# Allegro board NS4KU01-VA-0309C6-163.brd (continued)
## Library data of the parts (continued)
AB1 AB2 AB5 AB6 AB9 AB10 B2 B4 B8-B11 B19 B22 R15-R17 R20 R25 R26 R43 R46 R51 R55 R102 R106 R125 R145 R165 R182 R198 R230 R235 R245 R264 R329 R418 R477 R480 R514 R532 R549 R562 R563 R638 R670-R672 R3406 R3416 R3425 R3432 R3437 R3443 R3447 R3448 RT1 RT2 RT6 RT7 = M-R0603
AB4 AB7 AB8 AB11-AB17 AR3-AR15 B1 B5 B16-B18 ER1 ER2 R1-R14 R18 R19 R21-R24 R27-R38 R41 R42 R50 R52-R54 R56-R77 R79-R83 R85-R101 R103-R105 R107-R124 R126-R136 R138-R144 R147-R155 R157-R161 R163 R164 R167 R168 R170 R171 R173 R174 R176 R177 R179 R180 R184 R185 R187-R197 R199-R202 R204 R205 R207 R210-R229 R231-R234 R236-R244 R246-R258 R260-R263 R265-R328 R330-R392 R395-R414 R416 R420-R432 R434-R443 R448-R457 R460-R467 R469 R472-R476 R478 R479 R481-R513 R515-R531 R533 R534 R537 R539-R542 R545-R548 R550-R554 R557-R559 R561 R564-R568 R576-R579 R581-R604 R621 R622 R625 R637 R639 R643 R645-R648 R650 R651 R653 R658 R660 R668 R669 R687-R691 R695-R701 R710 R738-R743 R745 R784 R837-R844 R3058 R3085 R3087 R3095 R3152-R3154 R3160 R3161 R3163 R3164 R3197 R3198 R3201 R3214 R3232 R3239 R3243 R3247-R3253 R3255 R3258 R3278-R3281 R3294 R3310 R3321-R3323 R3370 R3386 R3401-R3403 R3405 R3407-R3410 R3413-R3415 R3417 R3421 R3422 R3426 R3428-R3431 R3433 R3434 R3436 R3439 R3440 R3442 R3444-R3446 R3449-R3451 R3527 = M-R0402
AC2-AC4 AC6 C2 C5 C8-C10 C13 C23 C32 C33 C50 C71 C89 C90 C94 C105 C114 C119 C127 C128 C135-C137 C144 C156 C158 C161 C163 C166 C176 C179 C180 C189 C192 C193 C198 C201 C205 C213 C214 C226 C229 C231 C240 C242 C253 C268 C278 C307 C316 C317 C334 C341 C363 C364 C375 C378-C381 C383 C390 C391 C401 C403 C409 C410 C414 C422 C442 C444 C445 C447 C449 C453 C455 C470 C471 C476 C480 C481 C483 C484 C488 C509 C512 C532 C540 C542 C547 C559 C561 C562 C564-C566 C570 C571 C575 C577 C579 C584 C588 C590 C622 C628 C632 C3492 C3493 C3497 C3504 C3671 C3682 C3703 C3704 C3866 C3867 C3911-C3918 C3920 C3921 C3930-C3933 C3936 C3937 C3945 = M-C0603
AC5 AC7 AC8 C1 C3 C4 C6 C7 C11 C12 C14-C22 C25 C26 C28-C30 C36 C37 C39 C42 C43 C46-C49 C53 C54 C56-C58 C62-C69 C72-C87 C102 C106-C108 C118 C125 C131 C133 C134 C138-C143 C145-C147 C149-C151 C153 C154 C157 C159 C160 C162 C164 C165 C167 C168 C171 C172 C174 C175 C177 C178 C181-C186 C202-C204 C206-C209 C212 C215 C218 C222 C225 C227 C228 C230 C232-C239 C241 C245-C252 C255-C265 C269-C273 C279 C281-C290 C292 C293 C305 C318 C319 C321 C322 C325 C332 C333 C335 C336 C338-C340 C342-C349 C351 C353 C354 C356-C359 C361 C362 C365-C370 C372-C374 C377 C382 C384 C385 C393-C400 C402 C404-C406 C411-C413 C417 C418 C421 C423 C431-C435 C438 C441 C443 C450-C452 C454 C456 C458-C469 C472-C475 C477-C479 C482 C485-C487 C490 C491 C493-C503 C505-C508 C510 C513-C531 C534-C539 C541 C543-C546 C548-C554 C563 C573 C580 C586 C592 C597 C613 C614 C616-C618 C623 C626 C627 C631 C633-C639 C649 C653 C654 C693-C696 C781 C782 C1205 C1206 C3400 C3401 C3404-C3407 C3491 C3494-C3496 C3498-C3503 C3535 C3579 C3658-C3662 C3672-C3675 C3680 C3681 C3683-C3697 C3701 C3702 C3705 C3706 C3713-C3715 C3720 C3721 C3773 C3783 C3883 C3919 C3922-C3929 C3934 C3935 C3938-C3940 EC1 EC2 = M-C0402
ANT1 = I-PEX-20431
AUDR1 = AUDIO_6P_SANTA-313072-1
B3 B7 B12 B13 B15 B20 = M-R0805: User Part Number: ***; Tolerance: ***
B6 = FCI1608
B24 B25 C35 C38 C41 C45 C92 C93 C97 C104 C109 C113 C115 C116 C121 C123 C126 C132 C152 C155 C169 C170 C173 C190 C194 C195 C200 C220 C221 C223 C243 C244 C254 C266 C267 C277 C294 C295 C306 C308 C315 C323 C331 C352 C355 C371 C386-C389 C415 C416 C420 C424-C428 C430 C436 C437 C448 C457 C492 C504 C511 C533 C555 C556 C558 C560 C615 C629 C650 PS3 = M-C0805
BAT1 = WFN-25_14P
C196 C3707-C3711 = SCE6_3X5_8MM
C583 C589 C591 C593 C594 C619-C621 = M-D7343: Tolerance: ***; User Part Number: ***
CN1 = CON_51625-18P_ACES
CN3 = CON_WB_3H125_85204-03001_ACES
CN4 = CON_6916K-Q06N-07L
CN5 = CON_WB_2H125_85204-02001_ACES
CN6 = CON_WB-6H80_88460-06001_ACES
CN7 = CON_FFC_6712K-X40N-07X
CN8 = CON_WB_10H80_S-88460-1001_ACES
CN9 = CON22_1D27_HDD_TBF0
CN11 = DDR4_SODIMM_REV_260PIN_H5P2MM
CN13 = TF_M2_KEY-B_2280_3H
CN14 = TF_M2_KEY-E_2230_3H
CN33 = CON2-2_50278-002XX-ACES
CRDR1 = CON_1IN1-R-NPS_DSD2-B_TAISOL
CRDR2 = CON_1IN1-R-PS_CS2001_ATE
D1 = SK34A
D4 D15 D19 = M-SOT23
D6 D16-D18 D26 D34 D41 D42 = 4148_WSP_0805
D7-D13 = DIODE-AZ5315-02F
D14 D20 D21 = D0402_AC
D23 = SOD_123_2D0
DCIN1 = POWERJACK_W059
ED3-ED6 = D0402
H1 H2 H4 H5 H8 H10 = TC296BC236D118
H3 H6 H7 = TC276BC236D165
H9 = HOLEO312X300DO132X120
H11 = C197D87
H24 = HOLEC276BC166D146
HDMI1 = CON19-4_0D5_0D55_HDMI_SA0127
JP10 JP13 JP14 JP17 = TOPOPEN-157X20
JP11 JP12 = TOPOPEN_20X30
KBT1 = CON24-2_1D0_DYS_W058
L1 L2 L7-L9 L26-L28 L31 = CHOKE-7X7_8X3_5
L11-L14 L16-L21 L25 L29 L32 L49 = CHOKE-4P_2X1_2X1_2
L23 = WSRPG0402-1R0M-H
LED1 = LED_19-223_S2T1D-C30_2T
LED2 LED3 = 19-113: Tolerance: ***; User Part Number: ***
LID1 = M-SOT23-3L: Tolerance: ***; User Part Number: ***
M3-M6 M9 M10 M13 M14 = M-MARK1
PJP2 PJP6 PJP10-PJP12 PJP36 = TOPSHORT_20X30
PJP17 PJP18 = TOPOPEN_20X157
Q1 Q11 Q15 Q16 Q18 Q24 Q25 Q27 Q39 Q59 = SOT363
Q4 Q12 Q14 Q19 Q20 Q26 Q28-Q30 Q32 Q33 Q35-Q38 Q40 Q49-Q54 Q56-Q58 Q151 Q152 = M-SOT23G
Q6 = M-SOT23A: User Part Number: ***; Tolerance: ***
Q10 Q17 = M-SC70-5
Q13 Q21 Q22 Q55 Q156 = M-SOT23A: Tolerance: ***; User Part Number: ***
Q31 Q34 Q41 Q42 Q47 Q48 Q61 = PDFN-8P_B3X3_D65
Q43-Q46 Q60 Q62 Q63 = PQFN8-PPS
R419 R471 RCH1 = M-R1206
S1-S28 S31-S54 = SCON2S
SBCN1 = CON12-2_0D5_50501ACES
SBCN2 = CON_FFC-DYS-W003-14P_D5
SPK1 = CON_WB_4H125_50278-0040N_ACES
SW1 = SWITCH_T-V_TME-533K-Q-TR_DIP
TA1-TA26 TA28 TA29 TB1-TB27 TB29 TC1-TC32 = VIA16
TP1-TP21 TP23 TP24 TP26-TP29 TP33-TP43 TP45-TP84 = TP12T
TP183-TP190 TP200 TP201 TP209 = TP20
U1 = VQFN40-3_0D4_5D0X5D0MCM
U2 = M-SO8
U3 U20 = M-SOP8B
U4 U5 U14 = DFN3X2-14L
U8 U23 = M-SO8_EP
U9 U18 = UQFN16_0D4_3X3
U11 = SKL_42X24_P65_1356
U12 = DFN3-10EP_0-5_2
U13 = TQFN32-2_4X4_GS9271
U15 = M-SOT23-5: User Part Number: ***
U19 = LGA16_3X3_D5
U25 = QFPS128-04M-60: User Part Number: ***
U26 = M-MSOP8: User Part Number: ***
U28 = M-TSSOP28-0_65-6_4MM
U31 = SOT-23-5
U32 = TSOT23-8
U33 = QFN48_D4-6X6
U109 = QFN40-1_0D4_5D0X5D0_OZ8283
U110 = QFN16-1_0D4_2D5X2D5_OZ8002
U1634 = BGA_49_0D5_4D1X4D4
U1635-U1638 = FBGA96_0D8_16X9_DDR4SDRAM
USB2R1 USB2R2 = CON4-4_0D7_2D0_USB_A0315
USB3R1 = CON_SUSB_3SR_UEA1111-R04012_FOX
WIFI1 = RL-UM02WBS-8723BU-1
Y1 Y6 = SMD_CRYSTAL-TXC-4P_3D2X2D5
Y3 = XTAL_CS3215_2P

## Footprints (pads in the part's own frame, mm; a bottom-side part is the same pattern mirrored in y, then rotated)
19-113
  rect 0.813x0.813 smd: A(-0.75,0) C(0.75,0)
4148_WSP_0805
  rect 0.762x1.651 smd: A(-0.991,0) C(0.991,0)
AUDIO_6P_SANTA-313072-1
  oval 1x1.75 hole 0.5x1.25: 1(-4.55,-3.045) 2(4.15,-4.155) 3(4.15,-1.155) 4(4.15,2.855) 5(-4.55,-0.625) 6(-4.55,3.255)
BGA_49_0D5_4D1X4D4
  round 0.254 smd: A1(-1.5,1.5) A2(-1,1.5) A3(-0.5,1.5) A4(0,1.5) A5(0.5,1.5) A6(1,1.5) A7(1.5,1.5) B1(-1.5,1) B2(-1,1) B3(-0.5,1) B4(0,1) B5(0.5,1) B6(1,1) B7(1.5,1) C1(-1.5,0.5) C2(-1,0.5) C3(-0.5,0.5) C4(0,0.5) C5(0.5,0.5) C6(1,0.5) C7(1.5,0.5) D1(-1.5,0) D2(-1,0) D3(-0.5,0) D4(0,0) D5(0.5,0) D6(1,0) D7(1.5,0) E1(-1.5,-0.5) E2(-1,-0.5) E3(-0.5,-0.5) E4(0,-0.5) E5(0.5,-0.5) E6(1,-0.5) E7(1.5,-0.5) F1(-1.5,-1) F2(-1,-1) F3(-0.5,-1) F4(0,-1) F5(0.5,-1) F6(1,-1) F7(1.5,-1) G1(-1.5,-1.5) G2(-1,-1.5) G3(-0.5,-1.5) G4(0,-1.5) G5(0.5,-1.5) G6(1,-1.5) G7(1.5,-1.5)
C197D87
  round 5.004 hole 2.21: 1(0,0)
CHOKE-4P_2X1_2X1_2
  rect 0.914x0.406 smd: 1(-0.85,0.4) 2(0.85,0.4) 3(0.85,-0.4) 4(-0.85,-0.4)
CHOKE-7X7_8X3_5
  rect 3.505x2.515 smd: 1(0,3.1) 2(0,-3.1)
CON2-2_50278-002XX-ACES
  rect 0.8x1.9 smd: 1(-0.625,4.925) 2(0.625,4.925)
  rect 1.3x3.35 smd: S1(-3.475,0) S2(3.475,0)
CON4-4_0D7_2D0_USB_A0315
  round 1.3 hole 0.7: 1(3.5,8.7) 2(1,8.7) 3(-1,8.7) 4(-3.5,8.7)
  oval 1.4x2.4 hole 0.8x1.8: S1(6.4,7.8) S2(-6.4,7.8)
  oval 1.4x3.2 hole 0.8x2.6: S3(7.85,0) S4(-7.85,0)
CON12-2_0D5_50501ACES
  rect 0.3x1.3 smd: 1(-2.75,2.8) 2(-2.25,2.8) 3(-1.75,2.8) 4(-1.25,2.8) 5(-0.75,2.8) 6(-0.25,2.8) 7(0.25,2.8) 8(0.75,2.8) 9(1.25,2.8) 10(1.75,2.8) 11(2.25,2.8) 12(2.75,2.8)
  rect 1.8x1.4 smd: S1(-4.55,0) S2(4.55,0)
CON19-4_0D5_0D55_HDMI_SA0127
  rect 0.8x0.8 hole 0.55: 1(-4.5,-0.05)
  round 0.8 hole 0.55: 2(-4,1.15) 3(-3.5,-0.05) 4(-3,1.15) 5(-2.5,-0.05) 6(-2,1.15) 7(-1.5,-0.05) 8(-1,1.15) 9(-0.5,-0.05) 10(0,1.15) 11(0.5,-0.05) 12(1,1.15) 13(1.5,-0.05) 14(2,1.15) 15(2.5,-0.05) 16(3,1.15) 17(3.5,-0.05) 18(4,1.15) 19(4.5,-0.05)
  oval 1.8x3.2 hole 1x2.4: S1(-7.25,0.72) S2(7.25,0.72)
  oval 1.8x3 hole 1x2.2: S3(-9.25,-6.13) S4(9.25,-6.13)
CON22_1D27_HDD_TBF0
  oval 1.194x1.6 hole 0.61x1.016: H1(20.191,4.549) H2(-17.229,4.549)
  oval 1.016x1.524 hole 0.813: P1(-0.423,3.599) P2(0.847,3.599) P3(2.117,3.599) P4(3.387,3.599) P5(4.657,3.599) P6(5.927,3.599) P7(7.197,3.599) P8(8.467,3.599) P9(9.737,3.599) P10(11.007,3.599) P11(12.277,3.599) P12(13.547,3.599) P13(14.817,3.599) P14(16.087,3.599) P15(17.357,3.599) S1(-14.393,3.599) S2(-13.123,3.599) S3(-11.853,3.599) S4(-10.583,3.599) S5(-9.313,3.599) S6(-8.043,3.599) S7(-6.773,3.599)
CON24-2_1D0_DYS_W058
  rect 0.3x1.4 smd: 1(-11.5,3.41) 2(-10.5,3.41) 3(-9.5,3.41) 4(-8.5,3.41) 5(-7.5,3.41) 6(-6.5,3.41) 7(-5.5,3.41) 8(-4.5,3.41) 9(-3.5,3.41) 10(-2.5,3.41) 11(-1.5,3.41) 12(-0.5,3.41) 13(0.5,3.41) 14(1.5,3.41) 15(2.5,3.41) 16(3.5,3.41) 17(4.5,3.41) 18(5.5,3.41) 19(6.5,3.41) 20(7.5,3.41) 21(8.5,3.41) 22(9.5,3.41) 23(10.5,3.41) 24(11.5,3.41)
  rect 1.3x2.3 smd: S1(-13.6,0) S2(13.6,0)
CON_1IN1-R-NPS_DSD2-B_TAISOL
  round 1.194 hole 1.194 unplated: (-11.925,0)
  round 0.787 hole 0.787 unplated: (11.925,0)
  rect 0.813x1.803 smd: 1(-10.85,1.6) 2(-9.35,1.6) 3(-6.85,1.6) 4(-4.35,1.6) 5(-1.85,1.6) 6(0.65,1.6) 7(3.15,1.6) 8(5.65,1.6) 9(7.57,1.6) 10(9.27,1.6) 11(10.97,1.6)
  oval 1.092x2.21 hole 0.61x1.092: H1(-12.325,-2.9) H2(12.375,-2.9) H3(-12.15,-11.2) H4(12.2,-11.2)
CON_1IN1-R-PS_CS2001_ATE
  round 1 hole 0.991 unplated: (0,4) (0,-4)
  rect 1.6x0.7 smd: 1(-11,3.2) 2(-11,2.1) 3(-11,1) 4(-11,-0.1) 5(-11,-1.2) 6(-11,-2.3) 7(-11,-3.4) 8(-11,-4.5) 9(-11,-5.6)
  rect 1.4x1.2 smd: 10(-10,-6.8)
  rect 2.2x1.2 smd: 11(-0.5,-6.99) 13(-0.5,8.89)
  rect 1.397x1.194 smd: 12(-10,7.8)
CON_6916K-Q06N-07L
  rect 0.61x1.321 smd: 1(-2.5,0) 2(-1.5,0) 3(-0.5,0) 4(0.5,0) 5(1.5,0) 6(2.5,0)
  rect 1.803x1.397 smd: S1(-4.65,-2.65) S2(4.65,-2.65)
CON_51625-18P_ACES
  rect 0.305x0.864 smd: 1(-4.25,0) 2(-3.75,0) 3(-3.25,0) 4(-2.75,0) 5(-2.25,0) 6(-1.75,0) 7(-1.25,0) 8(-0.75,0) 9(-0.25,0) 10(0.25,0) 11(0.75,0) 12(1.25,0) 13(1.75,0) 14(2.25,0) 15(2.75,0) 16(3.25,0) 17(3.75,0) 18(4.25,0)
  rect 0.991x1.499 smd: S1(-6.04,-3.555) S2(6.04,-3.555)
CON_FFC-DYS-W003-14P_D5
  rect 0.305x0.889 smd: 1(-3.25,3.1) 2(-2.75,3.1) 3(-2.25,3.1) 4(-1.75,3.1) 5(-1.25,3.1) 6(-0.75,3.1) 7(-0.25,3.1) 8(0.25,3.1) 9(0.75,3.1) 10(1.25,3.1) 11(1.75,3.1) 12(2.25,3.1) 13(2.75,3.1) 14(3.25,3.1)
  rect 0.991x2.007 smd: S1(-5.35,0) S2(5.35,0)
CON_FFC_6712K-X40N-07X
  rect 0.305x1.295 smd: 1(9.75,2.15) 2(9.25,2.15) 3(8.75,2.15) 4(8.25,2.15) 5(7.75,2.15) 6(7.25,2.15) 7(6.75,2.15) 8(6.25,2.15) 9(5.75,2.15) 10(5.25,2.15) 11(4.75,2.15) 12(4.25,2.15) 13(3.75,2.15) 14(3.25,2.15) 15(2.75,2.15) 16(2.25,2.15) 17(1.75,2.15) 18(1.25,2.15) 19(0.75,2.15) 20(0.25,2.15) 21(-0.25,2.15) 22(-0.75,2.15) 23(-1.25,2.15) 24(-1.75,2.15) 25(-2.25,2.15) 26(-2.75,2.15) 27(-3.25,2.15) 28(-3.75,2.15) 29(-4.25,2.15) 30(-4.75,2.15) 31(-5.25,2.15) 32(-5.75,2.15) 33(-6.25,2.15) 34(-6.75,2.15) 35(-7.25,2.15) 36(-7.75,2.15) 37(-8.25,2.15) 38(-8.75,2.15) 39(-9.25,2.15) 40(-9.75,2.15)
  rect 1.803x1.397 smd: S1(11.4,-0.5) S2(-11.4,-0.5)
CON_SUSB_3SR_UEA1111-R04012_FOX
  round 1.219 hole 0.711: 1(3.5,1.5) 2(1,1.5) 3(-1,1.5) 4(-3.5,1.5) 5(-4,0) 6(-2,0) 7(0,0) 8(2,0) 9(4,0)
  oval 1.575x2.565 hole 0.813x1.803: H1(6.4,0.6) H2(-6.4,0.6)
  oval 1.829x3.607 hole 0.813x2.591: H3(7.85,-7.2) H4(-7.85,-7.2)
CON_WB-6H80_88460-06001_ACES
  rect 0.508x1.016 smd: 1(-2,0) 2(-1.2,0) 3(-0.4,0) 4(0.4,0) 5(1.2,0) 6(2,0)
  rect 1.194x1.702 smd: S1(-3.3,-1.95) S2(3.3,-1.95)
CON_WB_2H125_85204-02001_ACES
  rect 0.813x1.626 smd: 1(-0.625,0) 2(0.625,0)
  rect 1.93x3.048 smd: S1(-3.07,-2.9) S2(3.07,-2.9)
CON_WB_3H125_85204-03001_ACES
  rect 0.813x1.626 smd: 1(1.25,0) 2(0,0) 3(-1.25,0)
  rect 2.134x3.048 smd: S1(-3.8,-2.9) S2(3.8,-2.9)
CON_WB_4H125_50278-0040N_ACES
  rect 0.813x1.905 smd: 1(-1.865,4.925) 2(-0.615,4.925) 3(0.635,4.925) 4(1.885,4.925)
  rect 1.321x3.353 smd: S1(-4.715,0) S2(4.735,0)
CON_WB_10H80_S-88460-1001_ACES
  rect 0.61x1.549 smd: 1(-3.6,1.938) 2(-2.8,1.938) 3(-2,1.938) 4(-1.2,1.938) 5(-0.4,1.938) 6(0.4,1.938) 7(1.2,1.938) 8(2.001,1.938) 9(2.801,1.938) 10(3.601,1.938)
  rect 1.194x1.803 smd: S1(-4.9,-0.012) S2(4.902,-0.012)
D0402
  rect 0.61x0.559 smd: 1(-0.432,0) 2(0.432,0)
D0402_AC
  rect 0.61x0.559 smd: A(0.432,0) C(-0.432,0)
DDR4_SODIMM_REV_260PIN_H5P2MM
  round 0.254 hole 1.6 unplated: (-1.025,4.1)
  round 0.254 hole 1.092 unplated: (67.775,4.1)
  rect 0.305x1.753 smd: 1(0,0) 2(0.25,8.2) 3(0.5,0) 4(0.75,8.2) 5(1,0) 6(1.25,8.2) 7(1.5,0) 8(1.75,8.2) 9(2,0) 10(2.25,8.2) 11(2.5,0) 12(2.75,8.2) 13(3,0) 14(3.25,8.2) 15(3.5,0) 16(3.75,8.2) 17(4,0) 18(4.25,8.2) 19(4.5,0) 20(4.75,8.2) 21(5,0) 22(5.25,8.2) 23(5.5,0) 24(5.75,8.2) 25(6,0) 26(6.25,8.2) 27(6.5,0) 28(6.75,8.2) 29(7,0) 30(7.25,8.2) 31(7.5,0) 32(7.75,8.2) 33(8,0) 34(8.25,8.2) 35(8.5,0) 36(8.75,8.2) 37(9,0) 38(9.25,8.2) 39(9.5,0) 40(9.75,8.2) 41(10,0) 42(10.25,8.2) 43(10.5,0) 44(10.75,8.2) 45(11,0) 46(11.25,8.2) 47(11.5,0) 48(11.75,8.2) 49(12,0) 50(12.25,8.2) 51(12.5,0) 52(12.75,8.2) 53(13,0) 54(13.25,8.2) 55(13.5,0) 56(13.75,8.2) 57(14,0) 58(14.25,8.2) 59(14.5,0) 60(14.75,8.2) 61(15,0) 62(15.25,8.2) 63(15.5,0) 64(15.75,8.2) 65(16,0) 66(16.25,8.2) 67(16.5,0) 68(16.75,8.2) 69(17,0) 70(17.25,8.2) 71(17.5,0) 72(17.75,8.2) 73(18,0) 74(18.25,8.2) 75(18.5,0) 76(18.75,8.2) 77(19,0) 78(19.25,8.2) 79(19.5,0) 80(19.75,8.2) 81(20,0) 82(20.25,8.2) 83(20.5,0) 84(20.75,8.2) 85(21,0) 86(21.25,8.2) 87(21.5,0) 88(21.75,8.2) 89(22,0) 90(22.25,8.2) 91(22.5,0) 92(22.75,8.2) 93(23,0) 94(23.25,8.2) 95(23.5,0) 96(23.75,8.2) 97(24,0) 98(24.25,8.2) 99(24.5,0) 100(24.75,8.2) 101(25,0) 102(25.25,8.2) 103(25.5,0) 104(25.75,8.2) 105(26,0) 106(26.25,8.2) 107(26.5,0) 108(26.75,8.2) 109(27,0) 110(27.25,8.2) 111(27.5,0) 112(27.75,8.2) 113(28,0) 114(28.25,8.2) 115(28.5,0) 116(28.75,8.2) 117(29,0) 118(29.25,8.2) 119(29.5,0) 120(29.75,8.2) 121(30,0) 122(30.25,8.2) 123(30.5,0) 124(30.75,8.2) 125(31,0) 126(31.25,8.2) 127(31.5,0) 128(31.75,8.2) 129(32,0) 130(32.25,8.2) 131(32.5,0) 132(32.75,8.2) 133(33,0) 134(33.25,8.2) 135(33.5,0) 136(33.75,8.2) 137(34,0) 138(34.25,8.2) 139(34.5,0) 140(34.75,8.2) 141(35,0) 142(35.25,8.2) 143(35.5,0) 144(35.75,8.2) 145(38,0) 146(38.25,8.2) 147(38.5,0) 148(38.75,8.2) 149(39,0) 150(39.25,8.2) 151(39.5,0) 152(39.75,8.2) 153(40,0) 154(40.25,8.2) 155(40.5,0) 156(40.75,8.2) 157(41,0) 158(41.25,8.2) 159(41.5,0) 160(41.75,8.2) 161(42,0) 162(42.25,8.2) 163(42.5,0) 164(42.75,8.2) 165(43,0) 166(43.25,8.2) 167(43.5,0) 168(43.75,8.2) 169(44,0) 170(44.25,8.2) 171(44.5,0) 172(44.75,8.2) 173(45,0) 174(45.25,8.2) 175(45.5,0) 176(45.75,8.2) 177(46,0) 178(46.25,8.2) 179(46.5,0) 180(46.75,8.2) 181(47,0) 182(47.25,8.2) 183(47.5,0) 184(47.75,8.2) 185(48,0) 186(48.25,8.2) 187(48.5,0) 188(48.75,8.2) 189(49,0) 190(49.25,8.2) 191(49.5,0) 192(49.75,8.2) 193(50,0) 194(50.25,8.2) 195(50.5,0) 196(50.75,8.2) 197(51,0) 198(51.25,8.2) 199(51.5,0) 200(51.75,8.2) 201(52,0) 202(52.25,8.2) 203(52.5,0) 204(52.75,8.2) 205(53,0) 206(53.25,8.2) 207(53.5,0) 208(53.75,8.2) 209(54,0) 210(54.25,8.2) 211(54.5,0) 212(54.75,8.2) 213(55,0) 214(55.25,8.2) 215(55.5,0) 216(55.75,8.2) 217(56,0) 218(56.25,8.2) 219(56.5,0) 220(56.75,8.2) 221(57,0) 222(57.25,8.2) 223(57.5,0) 224(57.75,8.2) 225(58,0) 226(58.25,8.2) 227(58.5,0) 228(58.75,8.2) 229(59,0) 230(59.25,8.2) 231(59.5,0) 232(59.75,8.2) 233(60,0) 234(60.25,8.2) 235(60.5,0) 236(60.75,8.2) 237(61,0) 238(61.25,8.2) 239(61.5,0) 240(61.75,8.2) 241(62,0) 242(62.25,8.2) 243(62.5,0) 244(62.75,8.2) 245(63,0) 246(63.25,8.2) 247(63.5,0) 248(63.75,8.2) 249(64,0) 250(64.25,8.2) 251(64.5,0) 252(64.75,8.2) 253(65,0) 254(65.25,8.2) 255(65.5,0) 256(65.75,8.2) 257(66,0) 258(66.25,8.2) 259(66.5,0) 260(66.75,8.2)
  rect 3.505x4.597 smd: 261(-0.425,-7.9) 262(67.175,-7.9)
DFN3-10EP_0-5_2
  rect 0.279x1.27 smd: 1(-1,-1.729) 2(-0.5,-1.729) 3(0,-1.729) 4(0.5,-1.729) 5(1,-1.729) 6(1,1.729) 7(0.5,1.729) 8(0,1.729) 9(-0.5,1.729) 10(-1,1.729)
  rect 2.413x1.397 smd: 11(0,0)
DFN3X2-14L
  custom 0.152x0.152 smd: 1(-1,-1.1) 7(1,-1.1) 8(1,1.1) 14(-1,1.1)
  rect 0.203x0.813 smd: 2(-0.8,-1.1) 3(-0.4,-1.1) 4(0,-1.1) 5(0.4,-1.1) 6(0.8,-1.1) 9(0.8,1.1) 10(0.4,1.1) 11(0,1.1) 12(-0.4,1.1) 13(-0.8,1.1)
  rect 2.489x0.914 smd: S1(0,0)
DIODE-AZ5315-02F
  rect 0.225x0.35 smd: 1(-0.187,0.325) 2(0.187,0.325)
  rect 0.6x0.35 smd: 3(0,-0.325)
FBGA96_0D8_16X9_DDR4SDRAM
  round 0.35 smd: A1(-3.2,6) A2(-2.4,6) A3(-1.6,6) A7(1.6,6) A8(2.4,6) A9(3.2,6) B1(-3.2,5.2) B2(-2.4,5.2) B3(-1.6,5.2) B7(1.6,5.2) B8(2.4,5.2) B9(3.2,5.2) C1(-3.2,4.4) C2(-2.4,4.4) C3(-1.6,4.4) C7(1.6,4.4) C8(2.4,4.4) C9(3.2,4.4) D1(-3.2,3.6) D2(-2.4,3.6) D3(-1.6,3.6) D7(1.6,3.6) D8(2.4,3.6) D9(3.2,3.6) E1(-3.2,2.8) E2(-2.4,2.8) E3(-1.6,2.8) E7(1.6,2.8) E8(2.4,2.8) E9(3.2,2.8) F1(-3.2,2) F2(-2.4,2) F3(-1.6,2) F7(1.6,2) F8(2.4,2) F9(3.2,2) G1(-3.2,1.2) G2(-2.4,1.2) G3(-1.6,1.2) G7(1.6,1.2) G8(2.4,1.2) G9(3.2,1.2) H1(-3.2,0.4) H2(-2.4,0.4) H3(-1.6,0.4) H7(1.6,0.4) H8(2.4,0.4) H9(3.2,0.4) J1(-3.2,-0.4) J2(-2.4,-0.4) J3(-1.6,-0.4) J7(1.6,-0.4) J8(2.4,-0.4) J9(3.2,-0.4) K1(-3.2,-1.2) K2(-2.4,-1.2) K3(-1.6,-1.2) K7(1.6,-1.2) K8(2.4,-1.2) K9(3.2,-1.2) L1(-3.2,-2) L2(-2.4,-2) L3(-1.6,-2) L7(1.6,-2) L8(2.4,-2) L9(3.2,-2) M1(-3.2,-2.8) M2(-2.4,-2.8) M3(-1.6,-2.8) M7(1.6,-2.8) M8(2.4,-2.8) M9(3.2,-2.8) N1(-3.2,-3.6) N2(-2.4,-3.6) N3(-1.6,-3.6) N7(1.6,-3.6) N8(2.4,-3.6) N9(3.2,-3.6) P1(-3.2,-4.4) P2(-2.4,-4.4) P3(-1.6,-4.4) P7(1.6,-4.4) P8(2.4,-4.4) P9(3.2,-4.4) R1(-3.2,-5.2) R2(-2.4,-5.2) R3(-1.6,-5.2) R7(1.6,-5.2) R8(2.4,-5.2) R9(3.2,-5.2) T1(-3.2,-6) T2(-2.4,-6) T3(-1.6,-6) T7(1.6,-6) T8(2.4,-6) T9(3.2,-6)
FCI1608
  rect 1.016x1.016 smd: 1(-0.8,0) 2(0.8,0)
HOLEC276BC166D146
  round 7.01 hole 3.708: 1(0,0)
HOLEO312X300DO132X120
  oval 7.925x7.62 hole 3.353x3.048: 1(0,0)
I-PEX-20431
  rect 1.067x1.016 smd: 1(1.525,0) S2(-1.525,0)
  rect 2.235x1.067 smd: S1(0,-1.475) S3(0,1.475)
LED_19-223_S2T1D-C30_2T
  rect 1.092x0.61 smd: 1(0.95,0.45) 2(0.95,-0.45) 3(-0.95,-0.45) 4(-0.95,0.45)
LGA16_3X3_D5
  rect 0.66x0.33 smd: 1(-1.225,1) 2(-1.225,0.5) 3(-1.225,0) 4(-1.225,-0.5) 5(-1.225,-1) 9(1.225,-1) 10(1.225,-0.5) 11(1.225,0) 12(1.225,0.5) 13(1.225,1)
  rect 0.33x0.66 smd: 6(-0.5,-1.225) 7(0,-1.225) 8(0.5,-1.225) 14(0.5,1.226) 15(0,1.226) 16(-0.5,1.226)
M-C0402
  rect 0.559x0.508 smd: 1(-0.432,0) 2(0.432,0)
M-C0603
  rect 0.914x0.813 smd: 1(-0.787,0) 2(0.787,0)
M-C0805
  rect 1.245x1.6 smd: 1(-0.975,0) 2(0.975,0)
M-D7343
  rect 2.311x2.997 smd: 1(-3.2,0) 2(3.2,0)
M-MARK1
  round 1.016 smd: 1(0,0)
M-MSOP8
  rect 0.406x1.524 smd: 1(-0.975,-2.2) 2(-0.325,-2.2) 3(0.325,-2.2) 4(0.975,-2.2) 5(0.975,2.2) 6(0.325,2.2) 7(-0.325,2.2) 8(-0.975,2.2)
M-R0402
  rect 0.559x0.508 smd: 1(-0.432,0) 2(0.432,0)
M-R0603
  rect 0.914x0.813 smd: 1(-0.787,0) 2(0.787,0)
M-R0805
  rect 1.245x1.6 smd: 1(-0.975,0) 2(0.975,0)
M-R1206
  rect 1.6x1.702 smd: 1(-1.4,0) 2(1.4,0)
M-SC70-5
  rect 0.406x1.118 smd: 1(-0.65,-1) 2(0,-1) 3(0.65,-1) 4(0.65,1) 5(-0.65,1)
M-SO8
  rect 0.635x1.905 smd: 1(-1.905,-2.667) 2(-0.635,-2.667) 3(0.635,-2.667) 4(1.905,-2.667) 5(1.905,2.667) 6(0.635,2.667) 7(-0.635,2.667) 8(-1.905,2.667)
M-SO8_EP
  rect 0.635x1.905 smd: 1(-1.905,-2.667) 2(-0.635,-2.667) 3(0.635,-2.667) 4(1.905,-2.667) 5(1.905,2.667) 6(0.635,2.667) 7(-0.635,2.667) 8(-1.905,2.667)
  rect 3.683x2.362 smd: S1(0,0)
M-SOP8B
  oval 0.61x2.794 smd: 1(-1.905,-3.124) 2(-0.635,-3.124) 3(0.635,-3.124) 4(1.905,-3.124) 5(1.905,3.124) 6(0.635,3.124) 7(-0.635,3.124) 8(-1.905,3.124)
M-SOT23
  rect 0.762x0.762 smd: 1(-0.953,-1.143) 2(0.953,-1.143) 3(0,1.143)
M-SOT23-3L
  rect 1.016x1.016 smd: 1(-0.953,-1.27) 2(0,1.27) 3(0.953,-1.27)
M-SOT23-5
  rect 0.711x1.524 smd: 1(-0.953,-1.1) 2(0,-1.1) 3(0.953,-1.1) 4(0.953,1.1) 5(-0.953,1.1)
M-SOT23A
  rect 0.762x0.762 smd: B(-0.953,-1.143) C(0,1.143) E(0.953,-1.143)
M-SOT23G
  rect 0.762x0.762 smd: D(0,1.143) G(-0.953,-1.143) S(0.953,-1.143)
M-TSSOP28-0_65-6_4MM
  rect 0.356x1.194 smd: 1(-4.225,-3.2) 2(-3.575,-3.2) 3(-2.925,-3.2) 4(-2.275,-3.2) 5(-1.625,-3.2) 6(-0.975,-3.2) 7(-0.325,-3.2) 8(0.325,-3.2) 9(0.975,-3.2) 10(1.625,-3.2) 11(2.275,-3.2) 12(2.925,-3.2) 13(3.575,-3.2) 14(4.225,-3.2) 15(4.225,3.2) 16(3.575,3.2) 17(2.925,3.2) 18(2.275,3.2) 19(1.625,3.2) 20(0.975,3.2) 21(0.325,3.2) 22(-0.325,3.2) 23(-0.975,3.2) 24(-1.625,3.2) 25(-2.275,3.2) 26(-2.925,3.2) 27(-3.575,3.2) 28(-4.225,3.2)
PDFN-8P_B3X3_D65
  rect 0.406x0.762 smd: 1(-0.975,-1.58) 2(-0.325,-1.58) 3(0.325,-1.58) 4(0.975,-1.58) 5(0.975,1.58) 6(0.325,1.58) 7(-0.325,1.58) 8(-0.975,1.58)
  rect 2.616x2.007 smd: S1(0,0.253)
POWERJACK_W059
  round 1.8 hole 1.2: 1(0,7.075)
  oval 1.2x2.1 hole 0.6x1.5: 2(-4.45,3.175) 3(4.45,3.175) 4(-4.45,-3.325) 5(4.45,-3.325)
PQFN8-PPS
  custom 0.425x0.425 smd: 1(-1.905,-2.68)
  rect 0.635x1.702 smd: 2(-0.635,-2.68) 3(0.635,-2.68) 4(1.905,-2.68) 5(1.905,2.68) 6(0.635,2.68) 7(-0.635,2.68)
  custom 1.111x1.111 smd: 8(-1.905,2.68)
QFN16-1_0D4_2D5X2D5_OZ8002
  rect 0.8x0.2 smd: 1(-1.325,0.6) 2(-1.325,0.2) 3(-1.325,-0.2) 4(-1.325,-0.6) 9(1.325,-0.6) 10(1.325,-0.2) 11(1.325,0.2) 12(1.325,0.6)
  rect 0.2x0.8 smd: 5(-0.6,-1.325) 6(-0.2,-1.325) 7(0.2,-1.325) 8(0.6,-1.325) 13(0.6,1.325) 14(0.2,1.325) 15(-0.2,1.325) 16(-0.6,1.325)
  rect 1.35x1.35 smd: 17(0,0)
QFN40-1_0D4_5D0X5D0_OZ8283
  rect 0.75x0.2 smd: 1(-2.425,1.8) 2(-2.425,1.4) 3(-2.425,1) 4(-2.425,0.6) 5(-2.425,0.2) 6(-2.425,-0.2) 7(-2.425,-0.6) 8(-2.425,-1) 9(-2.425,-1.4) 10(-2.425,-1.8) 21(2.425,-1.8) 22(2.425,-1.4) 23(2.425,-1) 24(2.425,-0.6) 25(2.425,-0.2) 26(2.425,0.2) 27(2.425,0.6) 28(2.425,1) 29(2.425,1.4) 30(2.425,1.8)
  rect 0.2x0.75 smd: 11(-1.8,-2.425) 12(-1.4,-2.425) 13(-1,-2.425) 14(-0.6,-2.425) 15(-0.2,-2.425) 16(0.2,-2.425) 17(0.6,-2.425) 18(1,-2.425) 19(1.4,-2.425) 20(1.8,-2.425) 31(1.8,2.425) 32(1.4,2.425) 33(1,2.425) 34(0.6,2.425) 35(0.2,2.425) 36(-0.2,2.425) 37(-0.6,2.425) 38(-1,2.425) 39(-1.4,2.425) 40(-1.8,2.425)
  rect 3.5x3.5 smd: 41(0,0)
QFN48_D4-6X6
  rect 0.203x0.813 smd: 1(2.2,3) 2(1.8,3) 3(1.4,3) 4(1,3) 5(0.6,3) 6(0.2,3) 7(-0.2,3) 8(-0.6,3) 9(-1,3) 10(-1.4,3) 11(-1.8,3) 12(-2.2,3) 25(-2.2,-3) 26(-1.8,-3) 27(-1.4,-3) 28(-1,-3) 29(-0.6,-3) 30(-0.2,-3) 31(0.2,-3) 32(0.6,-3) 33(1,-3) 34(1.4,-3) 35(1.8,-3) 36(2.2,-3)
  rect 0.813x0.203 smd: 13(-3,2.2) 14(-3,1.8) 15(-3,1.4) 16(-3,1) 17(-3,0.6) 18(-3,0.2) 19(-3,-0.2) 20(-3,-0.6) 21(-3,-1) 22(-3,-1.4) 23(-3,-1.8) 24(-3,-2.2) 37(3,-2.2) 38(3,-1.8) 39(3,-1.4) 40(3,-1) 41(3,-0.6) 42(3,-0.2) 43(3,0.2) 44(3,0.6) 45(3,1) 46(3,1.4) 47(3,1.8) 48(3,2.2)
  rect 4.318x4.318 smd: S1(0,0)
QFPS128-04M-60
  rect 0.305x1.524 smd: 1(-6.248,-7.75) 32(6.248,-7.75) 65(6.248,7.75) 96(-6.248,7.75)
  rect 0.203x1.524 smd: 2(-5.8,-7.75) 3(-5.4,-7.75) 4(-5,-7.75) 5(-4.6,-7.75) 6(-4.2,-7.75) 7(-3.8,-7.75) 8(-3.4,-7.75) 9(-3,-7.75) 10(-2.6,-7.75) 11(-2.2,-7.75) 12(-1.8,-7.75) 13(-1.4,-7.75) 14(-1,-7.75) 15(-0.6,-7.75) 16(-0.2,-7.75) 17(0.2,-7.75) 18(0.6,-7.75) 19(1,-7.75) 20(1.4,-7.75) 21(1.8,-7.75) 22(2.2,-7.75) 23(2.6,-7.75) 24(3,-7.75) 25(3.4,-7.75) 26(3.8,-7.75) 27(4.2,-7.75) 28(4.6,-7.75) 29(5,-7.75) 30(5.4,-7.75) 31(5.8,-7.75) 66(5.8,7.75) 67(5.4,7.75) 68(5,7.75) 69(4.6,7.75) 70(4.2,7.75) 71(3.8,7.75) 72(3.4,7.75) 73(3,7.75) 74(2.6,7.75) 75(2.2,7.75) 76(1.8,7.75) 77(1.4,7.75) 78(1,7.75) 79(0.6,7.75) 80(0.2,7.75) 81(-0.2,7.75) 82(-0.6,7.75) 83(-1,7.75) 84(-1.4,7.75) 85(-1.8,7.75) 86(-2.2,7.75) 87(-2.6,7.75) 88(-3,7.75) 89(-3.4,7.75) 90(-3.8,7.75) 91(-4.2,7.75) 92(-4.6,7.75) 93(-5,7.75) 94(-5.4,7.75) 95(-5.8,7.75)
  rect 1.524x0.305 smd: 33(7.75,-6.248) 64(7.75,6.248) 97(-7.75,6.248) 128(-7.75,-6.248)
  rect 1.524x0.203 smd: 34(7.75,-5.8) 35(7.75,-5.4) 36(7.75,-5) 37(7.75,-4.6) 38(7.75,-4.2) 39(7.75,-3.8) 40(7.75,-3.4) 41(7.75,-3) 42(7.75,-2.6) 43(7.75,-2.2) 44(7.75,-1.8) 45(7.75,-1.4) 46(7.75,-1) 47(7.75,-0.6) 48(7.75,-0.2) 49(7.75,0.2) 50(7.75,0.6) 51(7.75,1) 52(7.75,1.4) 53(7.75,1.8) 54(7.75,2.2) 55(7.75,2.6) 56(7.75,3) 57(7.75,3.4) 58(7.75,3.8) 59(7.75,4.2) 60(7.75,4.6) 61(7.75,5) 62(7.75,5.4) 63(7.75,5.8) 98(-7.75,5.8) 99(-7.75,5.4) 100(-7.75,5) 101(-7.75,4.6) 102(-7.75,4.2) 103(-7.75,3.8) 104(-7.75,3.4) 105(-7.75,3) 106(-7.75,2.6) 107(-7.75,2.2) 108(-7.75,1.8) 109(-7.75,1.4) 110(-7.75,1) 111(-7.75,0.6) 112(-7.75,0.2) 113(-7.75,-0.2) 114(-7.75,-0.6) 115(-7.75,-1) 116(-7.75,-1.4) 117(-7.75,-1.8) 118(-7.75,-2.2) 119(-7.75,-2.6) 120(-7.75,-3) 121(-7.75,-3.4) 122(-7.75,-3.8) 123(-7.75,-4.2) 124(-7.75,-4.6) 125(-7.75,-5) 126(-7.75,-5.4) 127(-7.75,-5.8)
RL-UM02WBS-8723BU-1
  rect 1.27x1.016 smd: 1(-6.1,3.918) 2(-6.1,1.581) 3(-6.1,-1.059) 4(-6.1,-3.218) 5(6.1,3.418) 6(6.1,0.918) 7(6.1,-2.582) 8(6.1,-5.382)
  rect 1.016x1.27 smd: 9(3.654,-6.702) 10(2.384,-6.702) 11(1.114,-6.702) 12(-0.156,-6.702) 13(-1.426,-6.702) 14(-2.696,-6.702)
SCE6_3X5_8MM
  rect 1.626x3.556 smd: 1(0,-2.7) 2(0,2.7)
SCON2S
  custom 0.064x0.064 smd: 1(0,0.191) 2(0,-0.191)
SK34A
  rect 1.753x2.032 smd: A(2.025,0) C(-2.025,0)
SKL_42X24_P65_1356
  round 0.356 smd: A3(19.349,-11.314) A70(-19.852,-11.314) B2(19.832,-10.832) B71(-20.314,-10.852) BA1(20.314,10.852) BA71(-20.314,10.852) BB2(19.852,11.314) BB70(-19.852,11.314) C1(20.314,-10.349)
  round 0.33 smd: A4(18.699,-11.314) A69(-19.202,-11.314) AY1(20.314,10.202) AY71(-20.314,10.202) B3(19.197,-10.679) B70(-19.685,-10.685) BA2(19.685,10.685) BA70(-19.685,10.685) BB3(19.202,11.314) BB69(-19.202,11.314) C2(19.679,-10.197) C71(-20.314,-10.202) D1(20.314,-9.699)
  round 0.305 smd: A5(18.048,-11.314) A68(-18.552,-11.314) AA2(19.339,-0.511) AA4(18.363,-0.511) AA63(-15.112,-0.596) AA64(-15.763,-0.596) AA65(-16.413,-0.596) AA66(-17.063,-0.596) AA67(-17.713,-0.596) AA68(-18.364,-0.596) AA69(-19.014,-0.596) AA70(-19.664,-0.596) AA71(-20.314,-0.596) AB4(18.363,0.152) AB6(17.585,-0.133) AB7(16.935,-0.133) AB8(16.285,-0.133) AB9(15.635,-0.133) AB10(14.984,-0.133) AB11(14.334,-0.133) AB12(13.684,-0.133) AB13(13.034,-0.133) AB15(12.188,-0.009) AB16(11.538,-0.009) AB17(10.888,-0.009) AB18(10.237,-0.009) AB19(9.587,-0.009) AB20(8.937,-0.009) AB21(8.287,-0.009) AB62(-14.644,-0.138) AC3(18.689,0.815) AC63(-15.112,0.319) AC64(-15.763,0.319) AC65(-16.413,0.319) AC66(-17.063,0.319) AC67(-17.713,0.319) AC68(-18.364,0.319) AC69(-19.014,0.319) AC70(-19.664,0.319) AC71(-20.314,0.319) AD4(18.363,1.478) AD6(17.585,0.934) AD7(16.935,0.934) AD8(16.285,0.934) AD9(15.635,0.934) AD10(14.984,0.934) AD11(14.334,0.934) AD12(13.684,0.934) AD13(13.034,0.934) AD15(12.188,0.829) AD16(11.538,0.829) AD17(10.888,0.829) AD18(10.237,0.829) AD19(9.587,0.829) AD20(8.937,0.829) AD21(8.287,0.829) AD62(-14.644,0.776) AE62(-14.644,1.69) AE63(-15.112,1.233) AE64(-15.763,1.233) AE65(-16.413,1.233) AE66(-17.063,1.233) AE67(-17.713,1.233) AE68(-18.364,1.233) AE69(-19.014,1.233) AF2(19.339,2.141) AF4(18.363,2.141) AF6(17.585,2.001) AF7(16.935,2.001) AF8(16.285,2.001) AF9(15.635,2.001) AF10(14.984,2.001) AF11(14.334,2.001) AF12(13.684,2.001) AF13(13.034,2.001) AF15(12.188,1.668) AF16(11.538,1.668) AF17(10.888,1.668) AF18(10.237,1.668) AF19(9.587,1.668) AF20(8.937,1.668) AF21(8.287,1.668) AF63(-15.112,2.148) AF64(-15.763,2.148) AF65(-16.413,2.148) AF66(-17.063,2.148) AF67(-17.713,2.148) AF68(-18.364,1.939) AF69(-19.014,1.939) AG4(18.363,2.804) AG15(12.188,2.506) AG16(11.538,2.506) AG17(10.888,2.506) AG18(10.237,2.506) AG19(9.587,2.506) AG20(8.937,2.506) AG21(8.287,2.506) AG62(-14.644,2.605) AG69(-18.689,2.602) AH3(18.689,3.467) AH6(17.585,3.067) AH7(16.935,3.067) AH8(16.285,3.067) AH9(15.635,3.067) AH10(14.984,3.067) AH11(14.334,3.067) AH12(13.684,3.067) AH13(13.034,3.067) AH63(-15.112,3.062) AH64(-15.763,3.062) AH65(-16.413,3.062) AH66(-17.063,3.062) AH67(-17.713,3.062) AJ4(18.363,4.13) AJ15(12.188,3.344) AJ16(11.538,3.344) AJ17(10.888,3.344) AJ18(10.237,3.344) AJ19(9.587,3.344) AJ20(8.937,3.344) AJ21(8.287,3.344) AJ62(-14.644,3.519) AK6(17.585,4.007) AK7(16.935,4.007) AK8(16.285,4.007) AK9(15.635,4.007) AK10(14.984,4.007) AK11(14.334,4.007) AK12(13.684,4.007) AK13(13.034,4.007) AK15(12.188,4.182) AK16(11.538,4.182) AK17(10.888,4.182) AK18(10.237,4.182) AK19(9.587,4.182) AK20(8.937,4.182) AK21(8.287,4.182) AK22(7.596,4.009) AK23(6.681,4.009) AK25(5.767,4.009) AK27(4.852,4.009) AK28(3.938,4.009) AK30(3.024,4.009) AK32(2.109,4.009) AK33(1.195,4.009) AK35(0.28,4.009) AK37(-0.634,4.009) AK38(-1.548,4.009) AK40(-2.463,4.009) AK42(-3.377,4.009) AK43(-4.292,4.009) AK45(-5.206,4.009) AK46(-6.12,4.009) AK48(-7.035,4.009) AK50(-7.949,4.009) AK52(-8.864,4.009) AK53(-9.778,4.009) AK55(-10.692,4.009) AK56(-11.607,4.009) AK58(-12.521,4.009) AK60(-13.436,4.009) AK62(-14.46,4.144) AK63(-15.112,3.976) AK64(-15.763,3.976) AK65(-16.413,3.976) AK66(-17.063,3.976) AK67(-17.713,3.976) AK68(-18.364,3.829) AK69(-19.339,3.829) AL2(19.339,4.793) AL4(18.363,4.793) AL23(7.138,4.474) AL25(6.224,4.474) AL27(5.31,4.474) AL28(4.395,4.474) AL30(3.481,4.474) AL32(2.566,4.474) AL33(1.652,4.474) AL35(0.738,4.474) AL37(-0.177,4.474) AL38(-1.091,4.474) AL40(-2.006,4.474) AL42(-2.92,4.474) AL43(-3.834,4.474) AL45(-4.749,4.474) AL46(-5.663,4.474) AL48(-6.578,4.474) AL50(-7.492,4.474) AL52(-8.406,4.474) AL53(-9.321,4.474) AL55(-10.235,4.474) AL56(-11.15,4.474) AL58(-12.064,4.474) AL60(-12.978,4.474) AL61(-13.893,4.474) AL63(-15.112,4.845) AL64(-15.763,4.845) AL65(-16.413,4.845) AL66(-17.063,4.845) AM4(18.363,5.456) AM5(17.654,4.946) AM7(16.74,4.946) AM8(15.825,4.946) AM10(14.911,4.946) AM11(13.996,4.946) AM13(13.082,4.946) AM15(12.168,4.946) AM16(11.253,4.946) AM18(10.339,4.946) AM20(9.424,4.946) AM21(8.51,4.946) AM22(7.596,4.946) AM23(6.681,4.946) AM25(5.767,4.946) AM27(4.852,4.946) AM28(3.938,4.946) AM30(3.024,4.946) AM32(2.109,4.946) AM33(1.195,4.946) AM35(0.28,4.946) AM37(-0.634,4.946) AM38(-1.548,4.946) AM40(-2.463,4.946) AM42(-3.377,4.946) AM43(-4.292,4.946) AM45(-5.206,4.946) AM46(-6.12,4.946) AM48(-7.035,4.946) AM50(-7.949,4.946) AM52(-8.864,4.946) AM53(-9.778,4.946) AM55(-10.692,4.946) AM56(-11.607,4.946) AM58(-12.521,4.946) AM60(-13.436,4.946) AM61(-14.35,4.946) AM68(-18.039,5.056) AM69(-18.689,5.056) AN3(18.689,6.119) AN5(17.654,5.597) AN7(16.74,5.597) AN8(15.825,5.597) AN10(14.911,5.597) AN11(13.996,5.597) AN13(13.082,5.597) AN15(12.168,5.597) AN16(11.253,5.597) AN18(10.339,5.597) AN20(9.424,5.597) AN21(8.51,5.597) AN22(7.596,5.597) AN23(6.681,5.597) AN25(5.767,5.597) AN27(4.852,5.597) AN28(3.938,5.597) AN30(3.024,5.597) AN32(2.109,5.597) AN33(1.195,5.597) AN35(0.28,5.597) AN37(-0.634,5.597) AN38(-1.548,5.597) AN40(-2.463,5.597) AN42(-3.377,5.597) AN43(-4.292,5.597) AN45(-5.206,5.597) AN46(-6.12,5.597) AN48(-7.035,5.597) AN50(-7.949,5.597) AN52(-8.864,5.597) AN53(-9.778,5.597) AN55(-10.692,5.597) AN56(-11.607,5.597) AN58(-12.521,5.597) AN60(-13.436,5.597) AN61(-14.35,5.597) AN63(-15.264,5.597) AN65(-16.179,5.597) AN66(-17.093,5.597) AN68(-18.364,5.719) AN69(-19.014,5.719) AP4(18.363,6.782) AP5(17.654,6.247) AP7(16.74,6.247) AP8(15.825,6.247) AP10(14.911,6.247) AP11(13.996,6.247) AP13(13.082,6.247) AP15(12.168,6.247) AP16(11.253,6.247) AP18(10.339,6.247) AP20(9.424,6.247) AP21(8.51,6.247) AP22(7.596,6.247) AP23(6.681,6.247) AP25(5.767,6.247) AP27(4.852,6.247) AP28(3.938,6.247) AP30(3.024,6.247) AP32(2.109,6.247) AP33(1.195,6.247) AP35(0.28,6.247) AP37(-0.634,6.247) AP38(-1.548,6.247) AP40(-2.463,6.247) AP42(-3.377,6.247) AP43(-4.292,6.247) AP45(-5.206,6.247) AP46(-6.12,6.247) AP48(-7.035,6.247) AP50(-7.949,6.247) AP52(-8.864,6.247) AP53(-9.778,6.247) AP55(-10.692,6.247) AP56(-11.607,6.247) AP58(-12.521,6.247) AP60(-13.436,6.247) AP61(-14.35,6.247) AP63(-15.264,6.247) AP65(-16.179,6.247) AP66(-17.093,6.247) AP68(-18.039,6.332) AP70(-19.258,6.332) AR5(17.654,6.897) AR7(16.74,6.897) AR8(15.825,6.897) AR10(14.911,6.897) AR11(13.996,6.897) AR13(13.082,6.897) AR15(12.168,6.897) AR16(11.253,6.897) AR18(10.339,6.897) AR20(9.424,6.897) AR21(8.51,6.897) AR22(7.596,6.897) AR23(6.681,6.897) AR25(5.767,6.897) AR27(4.852,6.897) AR28(3.938,6.897) AR30(3.024,6.897) AR32(2.109,6.897) AR33(1.195,6.897) AR35(0.28,6.897) AR37(-0.634,6.897) AR38(-1.548,6.897) AR40(-2.463,6.897) AR42(-3.377,6.897) AR43(-4.292,6.897) AR45(-5.206,6.897) AR46(-6.12,6.897) AR48(-7.035,6.897) AR50(-7.949,6.897) AR52(-8.864,6.897) AR53(-9.778,6.897) AR55(-10.692,6.897) AR56(-11.607,6.897) AR58(-12.521,6.897) AR60(-13.436,6.897) AR61(-14.35,6.897) AR63(-15.264,6.897) AR65(-16.179,6.897) AR66(-17.093,6.897) AR68(-18.364,6.945) AR69(-19.014,6.945) AT2(19.339,7.445) AT4(18.363,7.445) AT5(17.654,7.547) AT7(16.74,7.547) AT8(15.825,7.547) AT10(14.911,7.547) AT11(13.996,7.547) AT13(13.082,7.547) AT15(12.168,7.547) AT16(11.253,7.547) AT18(10.339,7.547) AT20(9.424,7.547) AT21(8.51,7.547) AT22(7.596,7.547) AT23(6.681,7.547) AT25(5.767,7.547) AT27(4.852,7.547) AT28(3.938,7.547) AT30(3.024,7.547) AT32(2.109,7.547) AT33(1.195,7.547) AT35(0.28,7.547) AT37(-0.634,7.547) AT38(-1.548,7.547) AT40(-2.463,7.547) AT42(-3.377,7.547) AT43(-4.292,7.547) AT45(-5.206,7.547) AT46(-6.12,7.547) AT48(-7.035,7.547) AT50(-7.949,7.547) AT52(-8.864,7.547) AT53(-9.778,7.547) AT55(-10.692,7.547) AT56(-11.607,7.547) AT58(-12.521,7.547) AT60(-13.436,7.547) AT61(-14.35,7.547) AT63(-15.264,7.547) AT65(-16.179,7.547) AT66(-17.093,7.547) AT68(-18.039,7.509) AT69(-18.689,7.509) AU4(18.363,8.108) AU5(17.654,8.198) AU7(16.74,8.198) AU8(15.825,8.198) AU10(14.911,8.198) AU11(13.996,8.198) AU13(13.082,8.198) AU15(12.168,8.198) AU16(11.253,8.198) AU18(10.339,8.198) AU20(9.424,8.198) AU21(8.51,8.198) AU22(7.596,8.198) AU23(6.681,8.198) AU25(5.767,8.198) AU27(4.852,8.198) AU28(3.938,8.198) AU30(3.024,8.198) AU32(2.109,8.198) AU33(1.195,8.198) AU35(0.28,8.198) AU37(-0.634,8.198) AU38(-1.548,8.198) AU40(-2.463,8.198) AU42(-3.377,8.198) AU43(-4.292,8.198) AU45(-5.206,8.198) AU46(-6.12,8.198) AU48(-7.035,8.198) AU50(-7.949,8.198) AU52(-8.864,8.198) AU53(-9.778,8.198) AU55(-10.692,8.198) AU56(-11.607,8.198) AU58(-12.521,8.198) AU60(-13.436,8.198) AU61(-14.35,8.198) AU63(-15.264,8.198) AU65(-16.179,8.198) AU66(-17.093,8.198) AV3(18.689,8.799) AV68(-18.029,8.711) AV69(-19.014,8.901) AV70(-19.664,8.901) AW1(20.314,9.551) AW5(17.781,8.911) AW6(17.13,9.038) AW7(16.564,9.363) AW8(15.986,9.038) AW9(15.416,9.363) AW10(14.753,9.038) AW11(14.143,9.363) AW12(13.565,9.038) AW13(12.995,9.363) AW14(12.332,9.038) AW15(11.723,9.363) AW16(11.145,9.038) AW17(10.575,9.363) AW18(9.912,9.038) AW20(9.302,9.363) AW21(8.724,9.038) AW22(8.154,9.363) AW23(7.466,9.038) AW25(6.828,9.363) AW26(6.264,9.038) AW27(5.601,9.363) AW28(4.988,9.038) AW29(4.374,9.363) AW30(3.711,9.038) AW31(3.148,9.363) AW32(2.485,9.038) AW33(1.847,9.363) AW34(1.283,9.038) AW35(0.62,9.363) AW36(0.007,9.038) AW37(-0.607,9.363) AW38(-1.269,9.038) AW39(-1.833,9.363) AW41(-2.471,9.038) AW42(-3.108,9.363) AW43(-3.672,9.038) AW44(-4.335,9.363) AW45(-4.949,9.038) AW46(-5.562,9.363) AW47(-6.163,9.038) AW48(-6.727,9.363) AW49(-7.355,9.038) AW50(-7.984,9.363) AW51(-8.548,9.038) AW52(-9.149,9.363) AW53(-9.762,9.038) AW54(-10.375,9.363) AW55(-11.038,9.038) AW56(-11.602,9.363) AW57(-12.24,9.038) AW59(-12.877,9.363) AW60(-13.441,9.038) AW61(-14.104,9.363) AW62(-14.718,9.038) AW63(-15.331,9.363) AW64(-15.994,9.038) AW65(-16.558,9.363) AW66(-17.093,8.9) AW67(-18.018,9.371) AW68(-18.622,9.622) AW69(-19.267,9.536) AW70(-19.685,10.035) AW71(-20.314,9.551) AY2(19.685,10.034) AY3(19.028,10.028) AY4(18.274,10.043) AY5(17.665,9.689) AY8(15.986,9.689) AY12(13.565,9.689) AY16(11.145,9.689) AY21(8.724,9.689) AY26(6.264,9.689) AY27(5.601,10.014) AY29(4.374,10.014) AY30(3.711,9.689) AY34(1.283,9.689) AY35(0.62,10.014) AY37(-0.607,10.014) AY38(-1.269,9.689) AY43(-3.672,9.689) AY44(-4.335,10.014) AY46(-5.562,10.014) AY47(-6.163,9.689) AY51(-8.548,9.689) AY52(-9.149,10.014) AY54(-10.375,10.014) AY55(-11.038,9.689) AY60(-13.441,9.689) AY61(-14.104,10.014) AY63(-15.331,10.014) AY64(-15.994,9.689) AY66(-17.221,9.689) AY68(-18.535,10.267) B5(18.048,-10.664) B6(17.467,-10.339) B10(14.989,-10.339) B14(12.511,-10.339) B18(10.033,-10.339) B22(7.555,-10.339) B26(5.077,-10.339) B30(2.599,-10.339) B34(0.121,-10.339) B39(-2.357,-10.339) B44(-4.835,-10.339) B48(-7.313,-10.339) B53(-9.791,-10.339) B58(-12.269,-10.339) B62(-14.747,-10.339) B66(-17.226,-10.339) B69(-19.035,-10.685) BA3(19.035,10.685) BA5(17.715,10.626) BA8(15.986,10.339) BA12(13.565,10.339) BA16(11.145,10.339) BA21(8.724,10.339) BA23(7.466,10.258) BA28(4.988,10.258) BA32(2.485,10.258) BA36(0.007,10.258) BA41(-2.471,10.258) BA45(-4.949,10.258) BA49(-7.355,10.339) BA53(-9.762,10.258) BA57(-12.24,10.258) BA62(-14.718,10.258) BA68(-19.035,10.685) BB4(18.551,11.314) BB68(-18.552,11.314) C4(18.615,-10.336) C5(18.048,-10.014) C7(16.791,-10.014) C8(16.228,-10.339) C9(15.664,-10.014) C11(14.313,-10.014) C12(13.75,-10.339) C13(13.186,-10.014) C15(11.835,-10.014) C16(11.272,-10.339) C17(10.708,-10.014) C19(9.357,-10.014) C20(8.794,-10.339) C21(8.23,-10.014) C23(6.879,-10.014) C24(6.316,-10.339) C25(5.752,-10.014) C27(4.401,-10.014) C28(3.838,-10.339) C29(3.274,-10.014) C31(1.923,-10.014) C32(1.36,-10.339) C33(0.796,-10.014) C36(-0.555,-10.014) C37(-1.118,-10.339) C38(-1.682,-10.014) C40(-3.033,-10.014) C41(-3.596,-10.339) C42(-4.16,-10.014) C45(-5.511,-10.014) C46(-6.074,-10.339) C47(-6.638,-10.014) C50(-7.989,-10.014) C51(-8.552,-10.339) C52(-9.116,-10.014) C54(-10.467,-10.014) C55(-11.03,-10.339) C56(-11.594,-10.014) C59(-12.945,-10.014) C60(-13.508,-10.339) C61(-14.072,-10.014) C63(-15.423,-10.014) C64(-15.987,-10.339) C65(-16.55,-10.014) C67(-18.485,-10.299) C68(-18.622,-9.622) C70(-19.685,-10.034) D3(19.339,-9.608) D4(18.691,-9.669) D5(18.09,-9.363) D6(17.441,-9.323) D7(16.791,-9.363) D8(16.228,-9.689) D9(15.664,-9.363) D10(14.989,-9.323) D11(14.313,-9.363) D12(13.75,-9.689) D13(13.186,-9.363) D14(12.511,-9.323) D15(11.835,-9.363) D16(11.272,-9.689) D17(10.708,-9.363) D18(10.033,-9.323) D19(9.357,-9.363) D20(8.794,-9.689) D21(8.23,-9.363) D22(7.555,-9.323) D23(6.879,-9.363) D24(6.316,-9.689) D25(5.752,-9.363) D26(5.077,-9.323) D27(4.401,-9.363) D28(3.838,-9.689) D29(3.274,-9.363) D30(2.599,-9.323) D31(1.923,-9.363) D32(1.36,-9.689) D33(0.796,-9.363) D34(0.121,-9.323) D36(-0.555,-9.363) D37(-1.118,-9.689) D38(-1.682,-9.363) D39(-2.357,-9.323) D40(-3.033,-9.363) D41(-3.596,-9.689) D42(-4.16,-9.363) D44(-4.835,-9.323) D45(-5.511,-9.363) D46(-6.074,-9.689) D47(-6.638,-9.363) D48(-7.313,-9.323) D50(-7.989,-9.363) D51(-8.552,-9.689) D52(-9.116,-9.363) D53(-9.791,-9.323) D54(-10.467,-9.363) D55(-11.03,-9.689) D56(-11.594,-9.363) D58(-12.269,-9.323) D59(-12.945,-9.363) D60(-13.508,-9.689) D61(-14.072,-9.363) D62(-14.747,-9.323) D63(-15.423,-9.363) D64(-15.987,-9.689) D65(-16.55,-9.363) D66(-17.226,-9.323) D67(-17.899,-10.014) D68(-19.267,-9.535) D69(-18.562,-8.971) D71(-20.314,-9.551) E1(20.314,-9.04) E2(19.664,-9.04) E3(19.014,-9.04) E5(17.654,-8.591) E6(16.74,-8.591) E8(15.825,-8.591) E10(14.911,-8.591) E11(13.996,-8.591) E13(13.082,-8.591) E15(12.168,-8.591) E16(11.253,-8.591) E18(10.339,-8.591) E20(9.424,-8.591) E21(8.51,-8.591) E22(7.596,-8.591) E23(6.681,-8.591) E25(5.767,-8.591) E27(4.852,-8.591) E28(3.938,-8.591) E30(3.024,-8.591) E32(2.109,-8.591) E33(1.195,-8.591) E35(0.28,-8.591) E37(-0.634,-8.591) E38(-1.548,-8.591) E40(-2.463,-8.591) E42(-3.377,-8.591) E43(-4.292,-8.591) E45(-5.206,-8.591) E46(-6.12,-8.591) E48(-7.035,-8.591) E50(-7.949,-8.591) E52(-8.864,-8.591) E53(-9.778,-8.591) E55(-10.692,-8.591) E56(-11.607,-8.591) E58(-12.521,-8.591) E60(-13.436,-8.591) E61(-14.35,-8.591) E63(-15.315,-8.655) E65(-16.331,-8.655) E66(-17.347,-8.655) E68(-17.899,-9.363) F2(19.339,-8.466) F4(18.363,-8.466) F5(17.654,-7.941) F6(16.74,-7.941) F8(15.825,-7.941) F10(14.911,-7.941) F11(13.996,-7.941) F13(13.082,-7.941) F15(12.168,-7.941) F16(11.253,-7.941) F18(10.339,-7.941) F20(9.424,-7.941) F21(8.51,-7.941) F22(7.596,-7.941) F23(6.681,-7.941) F25(5.767,-7.941) F27(4.852,-7.941) F28(3.938,-7.941) F30(3.024,-7.941) F32(2.109,-7.941) F33(1.195,-7.941) F35(0.28,-7.941) F37(-0.634,-7.941) F38(-1.548,-7.941) F40(-2.463,-7.941) F42(-3.377,-7.941) F43(-4.292,-7.941) F45(-5.206,-7.941) F46(-6.12,-7.941) F48(-7.035,-7.941) F50(-7.949,-7.941) F52(-8.864,-7.941) F53(-9.778,-7.941) F55(-10.692,-7.941) F56(-11.607,-7.941) F58(-12.521,-7.941) F60(-13.436,-7.941) F61(-14.35,-7.941) F63(-15.315,-8.005) F65(-16.331,-8.005) F66(-17.347,-8.005) F68(-18.562,-8.32) G4(18.363,-7.803) G5(17.654,-7.291) G6(16.74,-7.291) G8(15.825,-7.291) G10(14.911,-7.291) G11(13.996,-7.291) G13(13.082,-7.291) G15(12.168,-7.291) G16(11.253,-7.291) G18(10.339,-7.291) G20(9.424,-7.291) G21(8.51,-7.291) G22(7.596,-7.291) G23(6.681,-7.291) G25(5.767,-7.291) G27(4.852,-7.291) G28(3.938,-7.291) G30(3.024,-7.291) G32(2.109,-7.291) G33(1.195,-7.291) G35(0.28,-7.291) G37(-0.634,-7.291) G38(-1.548,-7.291) G40(-2.463,-7.291) G42(-3.377,-7.291) G43(-4.292,-7.291) G45(-5.206,-7.291) G46(-6.12,-7.291) G48(-7.035,-7.291) G50(-7.949,-7.291) G52(-8.864,-7.291) G53(-9.778,-7.291) G55(-10.692,-7.291) G56(-11.607,-7.291) G58(-12.521,-7.291) G60(-13.436,-7.291) G61(-14.35,-7.291) G63(-15.315,-7.354) G65(-16.331,-7.354) G66(-17.347,-7.354) G68(-18.364,-7.66) G69(-19.014,-7.66) H3(18.689,-7.14) H5(17.654,-6.641) H6(16.74,-6.641) H8(15.825,-6.641) H10(14.911,-6.641) H11(13.996,-6.641) H13(13.082,-6.641) H15(12.168,-6.641) H16(11.253,-6.641) H18(10.339,-6.641) H20(9.424,-6.641) H21(8.51,-6.641) H63(-15.315,-6.704) H65(-16.331,-6.704) H66(-17.347,-6.704) H69(-18.689,-7.096) J4(18.363,-6.477) J5(17.654,-5.99) J6(16.74,-5.99) J8(15.825,-5.99) J10(14.911,-5.99) J11(13.996,-5.99) J13(13.082,-5.99) J22(7.138,-6.827) J23(6.224,-6.827) J25(5.31,-6.827) J27(4.395,-6.827) J28(3.481,-6.827) J30(2.566,-6.827) J32(1.652,-6.827) J33(0.738,-6.827) J35(-0.177,-6.827) J37(-1.091,-6.827) J38(-2.006,-6.827) J40(-2.92,-6.827) J42(-3.834,-6.827) J43(-4.749,-6.827) J45(-5.663,-6.827) J46(-6.578,-6.827) J48(-7.492,-6.827) J50(-8.406,-6.827) J52(-9.321,-6.827) J53(-10.235,-6.827) J55(-11.15,-6.827) J56(-12.064,-6.827) J58(-12.978,-6.827) J60(-13.893,-6.827) J68(-18.362,-6.52) K15(12.188,-5.876) K16(11.538,-5.876) K17(10.888,-5.876) K18(10.237,-5.876) K19(9.587,-5.876) K20(8.937,-5.876) K21(8.287,-5.876) K22(7.596,-6.362) K23(6.681,-6.362) K25(5.767,-6.362) K27(4.852,-6.362) K28(3.938,-6.362) K30(3.024,-6.362) K32(2.109,-6.362) K33(1.195,-6.362) K35(0.28,-6.362) K37(-0.634,-6.362) K38(-1.548,-6.362) K40(-2.463,-6.362) K42(-3.377,-6.362) K43(-4.292,-6.362) K45(-5.206,-6.362) K46(-6.12,-6.362) K48(-7.035,-6.362) K50(-7.949,-6.362) K52(-8.864,-6.362) K53(-9.778,-6.362) K55(-10.692,-6.362) K56(-11.607,-6.362) K58(-12.521,-6.362) K60(-13.436,-6.362) K61(-14.35,-6.362) K63(-15.133,-6.054) K64(-15.783,-6.054) K65(-16.433,-6.054) K66(-17.084,-6.054) K67(-17.734,-6.054) K68(-18.352,-5.846) K70(-19.339,-5.744) L2(19.339,-5.814) L4(18.363,-5.814) L6(17.585,-5.34) L7(16.935,-5.34) L8(16.285,-5.34) L9(15.635,-5.34) L10(14.984,-5.34) L11(14.334,-5.34) L12(13.684,-5.34) L13(13.034,-5.34) L15(12.188,-5.038) L16(11.538,-5.038) L17(10.888,-5.038) L18(10.237,-5.038) L19(9.587,-5.038) L20(8.937,-5.038) L21(8.287,-5.038) L62(-14.644,-5.625) L63(-15.112,-5.168) L64(-15.763,-5.168) L65(-16.413,-5.168) L66(-17.063,-5.168) L67(-17.713,-5.168) L68(-18.364,-5.168) L69(-19.014,-5.168) L70(-19.664,-5.168) L71(-20.314,-5.168) M4(18.363,-5.151) M62(-14.644,-4.71) N3(18.689,-4.488) N6(17.585,-4.4) N7(16.935,-4.4) N8(16.285,-4.4) N9(15.635,-4.4) N10(14.984,-4.4) N11(14.334,-4.4) N12(13.684,-4.4) N13(13.034,-4.4) N15(12.188,-4.2) N16(11.538,-4.2) N17(10.888,-4.2) N18(10.237,-4.2) N19(9.587,-4.2) N20(8.937,-4.2) N21(8.287,-4.2) N63(-15.112,-4.253) N64(-15.763,-4.253) N65(-16.413,-4.253) N66(-17.063,-4.253) N67(-17.713,-4.253) N68(-18.364,-4.253) N69(-19.014,-4.253) N70(-19.664,-4.253) N71(-20.314,-4.253) P4(18.363,-3.825) P15(12.188,-3.362) P16(11.538,-3.362) P17(10.888,-3.362) P18(10.237,-3.362) P19(9.587,-3.362) P20(8.937,-3.362) P21(8.287,-3.362) P62(-14.644,-3.796) R6(17.585,-3.333) R7(16.935,-3.333) R8(16.285,-3.333) R9(15.635,-3.333) R10(14.984,-3.333) R11(14.334,-3.333) R12(13.684,-3.333) R13(13.034,-3.333) R63(-15.112,-3.339) R64(-15.763,-3.339) R65(-16.413,-3.339) R66(-17.063,-3.339) R67(-17.713,-3.339) R68(-18.364,-3.339) R69(-19.014,-3.339) R70(-19.664,-3.339) R71(-20.314,-3.339) T2(19.339,-3.162) T4(18.363,-3.162) T15(12.188,-2.523) T16(11.538,-2.523) T17(10.888,-2.523) T18(10.237,-2.523) T19(9.587,-2.523) T20(8.937,-2.523) T21(8.287,-2.523) T62(-14.644,-2.882) U4(18.363,-2.499) U6(17.585,-2.267) U7(16.935,-2.267) U8(16.285,-2.267) U9(15.635,-2.267) U10(14.984,-2.267) U11(14.334,-2.267) U12(13.684,-2.267) U13(13.034,-2.267) U63(-15.112,-2.424) U64(-15.763,-2.424) U65(-16.413,-2.424) U66(-17.063,-2.424) U67(-17.713,-2.424) U68(-18.364,-2.424) U69(-19.014,-2.424) U70(-19.664,-2.424) U71(-20.314,-2.424) V3(18.689,-1.836) V15(12.188,-1.685) V16(11.538,-1.685) V17(10.888,-1.685) V18(10.237,-1.685) V19(9.587,-1.685) V20(8.937,-1.685) V21(8.287,-1.685) V62(-14.644,-1.967) W4(18.363,-1.173) W6(17.585,-1.2) W7(16.935,-1.2) W8(16.285,-1.2) W9(15.635,-1.2) W10(14.984,-1.2) W11(14.334,-1.2) W12(13.684,-1.2) W13(13.034,-1.2) W63(-15.112,-1.51) W64(-15.763,-1.51) W65(-16.413,-1.51) W66(-17.063,-1.51) W67(-17.713,-1.51) W68(-18.364,-1.51) W69(-19.014,-1.51) W70(-19.664,-1.51) W71(-20.314,-1.51) Y15(12.188,-0.847) Y16(11.538,-0.847) Y17(10.888,-0.847) Y18(10.237,-0.847) Y19(9.587,-0.847) Y20(8.937,-0.847) Y21(8.287,-0.847) Y62(-14.644,-1.053)
  custom 0.064x0.064 smd: A6(17.467,-10.989) A7(16.791,-11.314) A9(15.664,-11.314) A10(14.989,-10.989) A11(14.313,-11.314) A13(13.186,-11.314) A14(12.511,-10.989) A15(11.835,-11.314) A17(10.708,-11.314) A18(10.033,-10.989) A19(9.357,-11.314) A21(8.23,-11.314) A22(7.555,-10.989) A23(6.879,-11.314) A25(5.752,-11.314) A26(5.077,-10.989) A27(4.401,-11.314) A29(3.274,-11.314) A30(2.599,-10.989) A31(1.923,-11.314) A33(0.796,-11.314) A34(0.121,-10.989) A36(-0.555,-11.314) A38(-1.682,-11.314) A39(-2.357,-10.989) A40(-3.033,-11.314) A42(-4.16,-11.314) A44(-4.835,-10.989) A45(-5.511,-11.314) A47(-6.638,-11.314) A48(-7.313,-10.989) A50(-7.989,-11.314) A52(-9.116,-11.314) A53(-9.791,-10.989) A54(-10.467,-11.314) A56(-11.594,-11.314) A58(-12.269,-10.989) A59(-12.945,-11.314) A61(-14.072,-11.314) A62(-14.747,-10.989) A63(-15.423,-11.314) A65(-16.55,-11.314) A66(-17.226,-10.989) A67(-17.901,-11.314) AA1(19.989,-0.511) AB1(20.314,0.152) AB2(19.664,0.152) AB3(19.014,0.152) AC1(19.989,0.815) AC2(19.339,0.815) AD1(20.314,1.478) AD2(19.664,1.478) AD3(19.014,1.478) AF1(19.989,2.141) AF70(-19.664,1.84) AF71(-20.314,1.84) AG1(20.314,2.804) AG2(19.664,2.804) AG3(19.014,2.804) AG70(-19.339,2.503) AG71(-19.989,2.503) AH1(19.989,3.467) AH2(19.339,3.467) AH68(-18.364,3.166) AH69(-19.014,3.166) AH70(-19.664,3.166) AH71(-20.314,3.166) AJ1(20.314,4.13) AJ2(19.664,4.13) AJ3(19.014,4.13) AK70(-19.989,3.829) AL1(19.989,4.793) AL68(-18.364,4.492) AL69(-19.014,4.492) AL70(-19.664,4.492) AL71(-20.314,4.492) AM1(20.314,5.456) AM2(19.664,5.456) AM3(19.014,5.456) AM70(-19.339,5.155) AM71(-19.989,5.155) AN1(19.989,6.119) AN2(19.339,6.119) AN70(-19.664,5.818) AN71(-20.314,5.818) AP1(20.314,6.782) AP2(19.664,6.782) AP3(19.014,6.782) AR70(-19.664,6.846) AR71(-20.314,6.846) AT1(19.989,7.445) AT70(-19.339,7.509) AT71(-19.989,7.509) AU1(20.314,8.108) AU2(19.664,8.108) AU3(19.014,8.108) AU68(-18.364,8.147) AU69(-19.014,8.172) AU70(-19.664,8.172) AU71(-20.314,8.172) AV1(20.314,8.828) AV2(19.364,8.799) AV71(-20.314,8.901) AW2(19.689,9.362) AW3(19.039,9.362) AY7(16.551,10.014) AY9(15.416,10.014) AY11(14.131,10.014) AY13(12.995,10.014) AY15(11.71,10.014) AY17(10.575,10.014) AY20(9.289,10.014) AY22(8.154,10.014) AY25(6.828,10.014) AY31(3.148,10.014) AY33(1.847,10.014) AY39(-1.833,10.014) AY42(-3.108,10.014) AY48(-6.789,10.014) AY50(-7.922,10.014) AY56(-11.602,10.014) AY59(-12.877,10.014) AY65(-16.558,10.014) AY67(-17.901,10.014) B7(16.791,-10.664) B9(15.664,-10.664) B11(14.313,-10.664) B13(13.186,-10.664) B15(11.835,-10.664) B17(10.708,-10.664) B19(9.357,-10.664) B21(8.23,-10.664) B23(6.879,-10.664) B25(5.752,-10.664) B27(4.401,-10.664) B29(3.274,-10.664) B31(1.923,-10.664) B33(0.796,-10.664) B36(-0.555,-10.664) B38(-1.682,-10.664) B40(-3.033,-10.664) B42(-4.16,-10.664) B45(-5.511,-10.664) B47(-6.638,-10.664) B50(-7.989,-10.664) B52(-9.116,-10.664) B54(-10.467,-10.664) B56(-11.594,-10.664) B59(-12.945,-10.664) B61(-14.072,-10.664) B63(-15.423,-10.664) B65(-16.55,-10.664) B67(-17.901,-10.664) BA4(18.366,10.689) BA6(17.173,10.258) BA7(16.61,10.664) BA9(15.416,10.664) BA10(14.753,10.258) BA11(14.189,10.664) BA13(12.995,10.664) BA14(12.332,10.258) BA15(11.768,10.664) BA17(10.575,10.664) BA18(9.912,10.258) BA20(9.348,10.664) BA22(8.154,10.664) BA25(6.828,10.664) BA26(6.165,10.339) BA27(5.502,10.664) BA29(4.473,10.664) BA30(3.811,10.339) BA31(3.148,10.664) BA33(1.847,10.664) BA34(1.184,10.339) BA35(0.521,10.664) BA37(-0.507,10.664) BA38(-1.17,10.339) BA39(-1.833,10.664) BA42(-3.108,10.664) BA43(-3.771,10.339) BA44(-4.434,10.664) BA46(-5.463,10.664) BA47(-6.126,10.339) BA48(-6.789,10.664) BA50(-7.922,10.664) BA51(-8.585,10.339) BA52(-9.248,10.664) BA54(-10.276,10.664) BA55(-10.939,10.339) BA56(-11.602,10.664) BA59(-12.877,10.664) BA60(-13.54,10.339) BA61(-14.203,10.664) BA63(-15.232,10.664) BA64(-15.895,10.339) BA65(-16.558,10.664) BA66(-17.221,10.339) BA67(-17.901,10.664) BB5(17.786,11.314) BB6(17.173,10.989) BB7(16.61,11.314) BB9(15.416,11.314) BB10(14.753,10.989) BB11(14.189,11.314) BB13(12.995,11.314) BB14(12.332,10.989) BB15(11.768,11.314) BB17(10.575,11.314) BB18(9.912,10.989) BB20(9.348,11.314) BB22(8.154,11.314) BB23(7.466,10.908) BB25(6.828,11.314) BB26(6.165,10.989) BB27(5.502,11.314) BB29(4.473,11.314) BB30(3.811,10.989) BB31(3.148,11.314) BB32(2.485,10.908) BB33(1.847,11.314) BB34(1.184,10.989) BB35(0.521,11.314) BB37(-0.507,11.314) BB38(-1.17,10.989) BB39(-1.833,11.314) BB41(-2.471,10.908) BB42(-3.108,11.314) BB43(-3.771,10.989) BB44(-4.434,11.314) BB46(-5.463,11.314) BB47(-6.126,10.989) BB48(-6.789,11.314) BB50(-7.922,11.314) BB51(-8.585,10.989) BB52(-9.248,11.314) BB54(-10.276,11.314) BB55(-10.939,10.989) BB56(-11.602,11.314) BB57(-12.24,10.908) BB59(-12.877,11.314) BB60(-13.54,10.989) BB61(-14.203,11.314) BB63(-15.232,11.314) BB64(-15.895,10.989) BB65(-16.558,11.314) BB66(-17.221,10.989) BB67(-17.901,11.314) E70(-19.664,-9.009) E71(-20.314,-8.901) F1(19.989,-8.466) F70(-19.212,-8.32) F71(-19.862,-8.384) G1(20.314,-7.803) G2(19.664,-7.803) G3(19.014,-7.803) G70(-19.664,-7.759) G71(-20.314,-7.759) H1(19.989,-7.14) H2(19.339,-7.14) H70(-19.339,-7.096) H71(-19.989,-7.096) J1(20.314,-6.477) J2(19.664,-6.477) J3(19.014,-6.477) J69(-19.014,-6.433) J70(-19.664,-6.433) J71(-20.314,-6.433) K71(-19.989,-5.744) L1(19.989,-5.814) M1(20.314,-5.151) M2(19.664,-5.151) M3(19.014,-5.151) N1(19.989,-4.488) N2(19.339,-4.488) P1(20.314,-3.825) P2(19.664,-3.825) P3(19.014,-3.825) T1(19.989,-3.162) U1(20.314,-2.499) U2(19.664,-2.499) U3(19.014,-2.499) V1(19.989,-1.836) V2(19.339,-1.836) W1(20.314,-1.173) W2(19.664,-1.173) W3(19.014,-1.173)
